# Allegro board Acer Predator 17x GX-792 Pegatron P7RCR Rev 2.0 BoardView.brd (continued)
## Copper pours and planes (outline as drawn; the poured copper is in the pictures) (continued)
PS_NVVDD_PHASE3 on TOP (solid shape): 150.98,183.75 150.98,182.35 151.36,181.97 153.4,181.97 153.9,182.48 156.7,182.48 156.95,182.23 156.95,180.19 160.2,176.94 160.2,168.66 159.49,167.95 149.75,167.95 149.21,168.5 149.21,171.05 147.55,172.7 147.55,179.46 153.65,179.46 153.65,179.4 153.66,179.34 153.67,179.28 153.7,179.22 153.73,179.16 153.77,179.11 153.81,179.06 153.86,179.02 153.91,178.99 153.97,178.96 154.03,178.94 154.1,178.93 154.16,178.92 154.22,178.93 154.29,178.94 154.35,178.96 154.4,178.99 154.46,179.02 154.51,179.06 154.55,179.11 154.59,179.16 154.62,179.22 154.64,179.28 154.66,179.34 154.67,179.4 154.67,179.46 154.66,179.53 154.64,179.59 154.62,179.65 154.59,179.71 154.55,179.76 154.51,179.8 154.46,179.84 154.4,179.88 154.35,179.91 154.29,179.93 154.22,179.94 154.16,179.94 154.1,179.94 154.03,179.93 153.97,179.91 153.91,179.88 153.86,179.84 153.81,179.8 153.77,179.76 153.73,179.71 153.7,179.65 153.67,179.59 153.66,179.53 153.65,179.46 147.55,179.46 147.55,183.62 147.81,183.88 150.86,183.88
PS_NVVDD_PHASE3 on BOTTOM (solid shape): 160.21,176.25 160.21,168.28 159.47,167.53 149.73,167.53 148.34,168.92 148.34,175.47 148.38,175.51 148.99,175.51 149.39,175.9 150.18,176.7 159.77,176.7
PS_NVVDD_PHASE4 on TOP (solid shape): 170.75,165.16 170.75,165.05 170.68,164.97 169.57,164.97 169.07,164.47 169.07,164.27 169.03,164.23 168.21,164.23 168.21,164.9 168.51,165.21 170.7,165.21
PS_NVVDD_PHASE4 on TOP (solid shape): outline of 112 points within 159.75,167.95 173.21,181.34
PS_NVVDD_PHASE4 on BOTTOM (solid shape): 173.24,176.57 173.24,168.59 172.12,167.47 163.56,167.47 161.34,169.68 161.34,175.22 161.65,175.53 162.14,175.53 162.51,175.9 162.51,175.99 163.4,176.88 172.93,176.88
SURGE_IN_C on IN1 (solid shape): 297.27,153.26 297.27,147.68 298.05,146.9 298.05,145.27 297.69,144.91 296.18,144.91 295.52,145.57 295.52,152.75 293.64,154.63 292,154.63 291.89,154.75 291.89,155.93 292.04,156.07 294.45,156.07
VGA_DDR_BST1 on TOP (solid shape): 248.07,81.13 247.78,80.84 247.53,80.48 247.53,79.38 247.35,79.2 247.02,79.2 246.81,79.41 246.81,80.61 247.27,81.07 247.47,81.07 247.77,81.23 247.86,81.33 247.86,81.63 248.07,81.63
VGA_DDR_BST1_R on TOP (solid shape): 244.86,81.03 245.67,81.03 245.78,80.92 246.13,80.92 246.42,80.63 246.42,80.12 246.33,80.03 245.64,80.03 245.56,80.07 245.54,80.16 245.44,80.52 245.08,80.62 245.04,80.61 245.01,80.62 244.38,80.62 244.13,80.88 244.13,81.13 244.28,81.29 244.61,81.29
VGA_DDR_BST2 on TOP (solid shape): 247.44,85.84 247.44,85.21 248.03,84.61 248.08,84.53 248.08,83.96 247.86,83.96 247.86,84.06 246.95,84.98 246.95,85.84 247,85.9 247.38,85.9
VGA_DDR_BST2_R on TOP (solid shape): 245.82,86.18 246.24,86.18 246.53,85.89 246.53,85.35 246.46,85.28 245.02,85.28 244.87,85.43 244.87,86.58 245.05,86.76 245.24,86.76
VGA_DDR_HG1 on TOP (solid shape): 248.48,80.72 248.47,80.71 248.47,80.01 248.4,79.94 247.88,79.94 247.8,80.02 247.8,80.3 247.89,80.52 247.97,80.6 248.27,81.11 248.27,81.64 248.48,81.64
VGA_DDR_HG1_R on TOP (solid shape): 225.89,90.48 225.89,88.15 225.63,87.89 224.36,87.89 224.2,88.05 224.2,90.06 224.7,90.56 225.81,90.56
VGA_DDR_HG1_R on TOP (solid shape): 248.77,79.18 248.77,78.93 248.91,78.79 248.91,78.43 248.81,78.33 248.49,78.33 247.8,79.02 247.8,79.47 247.88,79.54 248.41,79.54
VGA_DDR_HG2 on TOP (solid shape): 248.37,88.06 248.37,86.63 248.3,86.21 248.46,85.81 248.45,85.69 248.48,85.57 248.48,85.5 248.48,85.49 248.48,84 248.27,84 248.27,84.62 248.14,84.89 247.73,85.3 247.73,86.07 247.58,86.23 247.58,88.04 247.78,88.25 248.19,88.25
VGA_DDR_HG2_R on TOP (solid shape): 247.08,87.87 247.17,87.78 247.17,86.88 247.1,86.81 246.09,86.81 245.75,87.15 245.75,87.69 245.93,87.87 246.92,87.87
VGA_DDR_HG2_R on TOP (solid shape): 242.09,91.1 242.09,90.71 241.93,90.54 240.01,90.54 239.89,90.42 238.88,90.42 238.77,90.53 238.77,91.14 238.78,91.16 238.78,91.6 239.11,91.93 241.26,91.93
VGA_DDR_LG1 on TOP (solid shape): 247.59,82.33 247.04,82.33 246.91,82.25 246.51,81.85 246.26,81.85 245.97,82.14 245.97,82.35 246.17,82.55 247.59,82.55
VGA_DDR_LG1 on BOTTOM (solid shape): 220.12,100.25 220.12,99.79 219.97,99.65 218.36,99.65 217.91,99.2 216.87,99.2 216.72,99.35 216.72,99.75 216.8,99.83 217.27,99.83 217.86,100.42 219.95,100.42
VGA_DDR_LG2 on TOP (solid shape): 246.63,83.59 247.04,83.34 247.58,83.34 247.58,83.12 246.78,83.12 246.55,83.23 245.21,83.23 245.06,83.38 245.06,83.81 245.19,83.94 246.27,83.94
VGA_DDR_LG2 on BOTTOM (solid shape): 246.75,85.06 246.75,83.89 246.2,83.34 245.29,83.34 244.33,84.3 244.33,85.68 244.46,85.81 246.01,85.81
VGA_DDR_LX1 on TOP (solid shape): 225.86,96.78 225.86,95.51 226.12,95.26 226.12,94.83 225.86,94.57 225.86,91.27 225.79,91.19 224.43,91.19 223.8,90.56 219.25,90.56 218.79,91.02 218.79,94.95 219.21,95.37 219.21,96.86 219.59,97.24 220.96,97.24 221.04,97.31 225.33,97.31
VGA_DDR_LX1 on TOP (solid shape): 246.09,81.55 246.59,81.55 246.87,81.72 247.04,82.04 247.04,82.1 247.07,82.14 247.62,82.14 247.62,81.67 247.51,81.5 247.14,81.29 246.9,81.17 245.85,81.17 245.55,81.46 244.38,81.46 244.3,81.54 244.3,82 244.48,82.18 245.46,82.18
VGA_DDR_LX1 on BOTTOM (solid shape): 224.75,100.26 225.14,99.89 225.67,99.81 225.94,99.28 226.49,99.04 226.55,98.94 226.62,98.84 226.75,98.21 227.31,97.9 227.31,90.91 226.96,90.57 219.26,90.57 218.75,91.08 218.75,94.83 219.01,95.1 219.63,95.1 220.02,95.48 220.37,95.48 221.07,96.18 221.07,99.85 221.48,100.26
VGA_DDR_LX2 on TOP (solid shape): 244.61,86.98 244.61,85.45 245.08,84.98 246.25,84.98 247.49,83.73 247.59,83.73 247.59,83.52 247.07,83.52 246.92,83.64 246.31,84.24 243.9,84.24 243.49,83.83 240.62,83.83 239.43,82.64 239.43,82.57 239.21,82.35 238.09,82.35 238.08,82.35 237.8,82.35 237.8,82.35 237.23,82.35 236.78,82.8 236.6,82.8 236.56,82.84 235.59,82.84 235.46,82.97 235.46,86.1 235.64,86.27 238.39,86.27 238.77,86.65 238.77,89.59 238.94,89.77 240.14,89.77 240.27,89.91 241.68,89.91
VGA_DDR_LX2 on BOTTOM (solid shape): 233.79,94.47 238.74,94.47 239.12,94.09 239.76,94.09 239.96,93.89 239.96,90.66 240.42,90.2 242.96,90.2 243.59,89.57 243.59,85.22 241.29,82.93 241.29,82.04 240.39,81.13 236.45,81.13 236.2,81.39 236.2,82.9 236.07,83.03 236.07,85.1 236.02,85.15 236.02,85.66 235.82,85.86 234.1,85.86 229.08,90.88 228.23,90.88 228.07,91.04 228.07,94.47 228.2,94.6 233.66,94.6
VGA_DDR_RC1 on TOP (solid shape): 222.28,99.23 222.28,97.97 222.13,97.82 220.73,97.82 220.52,98.03 220.07,98.03 220.02,98.09 220.02,98.87 220.7,99.55 221.97,99.55
VGA_DDR_RC2 on BOTTOM (solid shape): 242.55,91.8 242.55,90.91 242.37,90.74 240.98,90.74 240.87,90.84 240.87,92.01 240.96,92.09 242.26,92.09
VGA_DDR_VCCP on TOP (solid shape): 245.03,83.05 246.47,83.05 246.71,82.94 247.59,82.94 247.59,82.73 246.47,82.73 246.39,82.74 246.3,82.73 245.88,82.73 245.57,82.42 244.25,82.42 244.07,82.6 244.07,83.14 244.23,83.3 244.78,83.3
VID_PLLVDD_GPU_AW27 on TOP (solid shape): 149.92,84.44 149.92,83.33 149.85,83.26 149.25,83.26 149.04,83.06 149.02,83.06 148.87,83.04 148.74,82.95 148.45,82.95 148.25,83.02 148.05,82.95 147.84,82.95 147.61,83.04 147.37,82.95 145.72,82.95 145.06,82.29 145.05,82.09 145.06,81.91 143.57,80.42 143.57,80.42 143.08,79.94 141.23,79.94 140.82,80.35 139.91,80.35 139.81,80.45 139.81,80.83 139.9,80.92 140.91,80.92 141.08,80.75 142.73,80.75 143.39,81.41 143.39,81.92 143.52,82.05 144.08,82.05 145.67,83.64 146.8,83.64 146.81,83.64 147,83.6 147.19,83.64 147.2,83.64 147.6,83.64 147.72,83.76 148.18,83.76 148.19,83.76 148.42,83.76 148.6,83.9 148.83,83.9 149.3,83.87 149.39,84.33 149.38,84.34 149.38,84.41 149.43,84.46 149.89,84.46
VID_PLLVDD_GPU_AW28 on TOP (solid shape): 150.51,84.3 150.57,84.19 150.66,84.12 150.66,81.84 150.52,81.7 150,81.7 149.32,81.02 145.45,81.02 145.36,80.93 145.35,80.92 145.25,80.85 145.17,80.75 145.17,80.74 144.82,80.39 144.81,80.39 144.68,80.3 144.6,80.17 144.59,80.16 144.53,80.1 144.53,79.08 144.35,78.9 143.69,78.9 143.64,78.95 143.64,80.23 145.14,81.73 146.05,81.73 146.24,81.68 146.43,81.73 146.69,81.73 146.7,81.73 146.85,81.69 147,81.73 147.01,81.73 148.06,81.73 148.27,81.64 148.5,81.71 148.53,81.73 149.29,81.73 149.52,81.96 149.64,81.96 149.95,82.28 149.98,82.28 149.98,82.42 150.06,82.51 150.06,84.17 150.23,84.34 150.48,84.34
VLDOIN on TOP (solid shape): 27.9,55.01 27.9,53.06 27.44,52.6 27.44,51.41 27.4,51.37 27.21,51.37 27.16,51.41 27.16,51.93 26.96,52.13 26.96,54.93 27.08,55.06 27.84,55.06
N60250715 on TOP (solid shape): 259.35,83.76 259.35,83.16 259.31,83.12 259.31,83.09 259.26,82.91 259.31,82.73 259.31,82.72 259.31,82.68 259.34,82.66 259.34,81.9 259.29,81.85 259.19,81.85 259.16,81.87 259.16,82.58 258.81,82.94 258.81,83.78 258.86,83.83 259.29,83.83
N60250719 on TOP (solid shape): 260.33,83.67 260.33,82.81 260.13,82.61 260.13,81.9 260.08,81.85 259.98,81.85 259.95,81.87 259.95,82.68 260.03,82.9 259.92,83.18 259.86,83.23 259.7,83.39 259.7,83.78 259.75,83.83 260.18,83.83
N65023456 on TOP (solid shape): 12.21,75.16 12.21,72.94 11.84,72.57 9.62,72.57 8.59,73.59 8.59,75.72 8.74,75.88 11.49,75.88
N125034509 on BOTTOM (solid shape): outline of 272 points within 76.09,113.65 79.79,118.27
N125034565 on TOP (solid shape): 80.28,122.22 80.28,121.7 80.32,121.66 80.32,121.41 80.15,121.24 79.21,121.24 79.03,121.06 77.87,121.06 77.74,121.19 77.74,121.6 77.82,121.67 78.94,121.67 79.04,121.78 79.04,121.84 79.66,122.46 80.04,122.46
N125034565 on BOTTOM (solid shape): 77.98,123.13 78,123.1 78,122.93 78.08,122.84 78.72,122.84 79.2,122.36 80,122.36 80.41,121.95 80.41,121.44 80.28,121.32 78.25,121.32 78,121.06 78,120.99 77.99,120.98 77.97,120.86 77.99,120.74 78,120.73 78,120.2 77.99,120.19 77.97,120.07 77.99,119.95 78,119.92 78.06,119.85 78.12,119.79 78.15,119.79 78.29,119.75 78.43,119.79 78.44,119.79 78.79,119.79 78.8,119.79 78.94,119.75 79.08,119.79 79.09,119.79 79.25,119.79 79.29,119.77 79.39,119.67 79.39,119.03 79.27,118.9 77.74,118.9 77.66,118.99 77.65,119 77.56,119.14 77.42,119.23 77.41,119.24 77.28,119.36 77.27,119.41 77.27,119.47 77.02,119.72 77.01,119.74 76.93,119.92 76.76,120.02 76.73,120.03 76.73,120.3 76.98,120.55 77,120.56 77.19,120.63 77.29,120.82 77.29,120.83 77.35,120.9 77.37,120.9 77.66,121.19 77.49,121.56 77.49,122.52 77.67,122.83 77.49,123.14 77.49,123.3 77.5,123.31 77.54,123.34 77.58,123.37 77.74,123.37
N126075660 on BOTTOM (solid shape): 239.27,49.9 239.27,49.79 240.06,49 241.08,49 241.48,48.6 242.42,48.6 242.73,48.9 245.31,48.9 245.32,48.9 245.32,48.39 245.31,48.38 243.41,48.38 243.41,48.38 242.81,48.38 242.32,47.89 241.36,47.89 241.36,47.9 240.87,48.38 239.6,48.38 239.09,48.89 238.93,48.91 238.93,49.06 238.93,49.23 238.82,49.33 238.82,49.37 238.78,49.41 238.78,50.06 238.88,50.16 239.02,50.16
N126076879 on IN2 (solid shape): outline of 658 points within 227.77,46.03 239.76,50.76
N126273757 on TOP (solid shape): 77.54,111.98 77.54,111.66 77.34,111.46 76.79,111.46 76.59,111.47 76.4,111.4 76.38,111.39 75.39,110.4 74.96,110.4 74.86,110.5 74.86,110.88 75.16,111.18 75.52,111.18 75.52,111.19 75.67,111.19 75.74,111.26 75.74,112.1 75.79,112.15 77.37,112.15
N126721746 on BOTTOM (solid shape): 74.81,113.57 75.04,113.47 75.26,113.57 75.46,113.57 75.6,113.48 75.76,113.48 75.79,113.49 75.96,113.32 75.96,113.06 75.71,112.81 74.17,112.81 74.1,112.88 74.1,113.1 74.46,113.46 74.47,113.47 74.56,113.51 74.63,113.57
N126721910 on BOTTOM (solid shape): 75.71,113.98 75.77,113.91 75.84,113.86 75.84,113.7 75.75,113.61 75.69,113.6 75.64,113.6 75.36,113.74 75.08,113.6 75.03,113.6 74.99,113.6 74.7,113.74 74.43,113.59 74.34,113.59 74.09,113.35 73.63,113.35 73.55,113.44 73.55,113.73 73.79,113.98
N129963392 on TOP (solid shape): 2.77,30.69 2.77,30.44 2.52,30.18 2.52,29.12 2.27,28.86 2.27,28.85 2.15,28.37 2.57,28.13 2.9,27.79 3.53,27.79 3.89,27.64 4.26,27.79 4.43,27.79 4.55,27.67 4.55,25.99 2.39,23.83 2.39,20.43 2.27,20.3 2.27,19.16 2.14,19.03 1.25,19.03 1.14,19.14 1.14,20.74 1.15,20.81 1.14,20.88 1.14,23.28 1.15,23.35 1.14,23.42 1.14,24.26 1.38,24.49 1.81,24.49 1.96,24.65 1.96,27.72 1.61,28.07 1.61,29.27 1.86,29.52 1.86,30.59 2.06,30.79 2.67,30.79
N136259332 on TOP (solid shape): 301.83,48.6 301.83,47.2 301.48,46.84 299.6,46.84 298.71,45.96 298.71,45.3 298.63,45.22 298.46,45.22 298.38,45.3 298.38,45.32 298.32,45.51 298.14,45.6 298.12,45.6 298.08,45.65 298.08,45.89 298.09,45.9 298.09,46.22 298.43,46.83 298.43,48.52 298.58,48.67 301.76,48.67
N138947971 on BOTTOM (solid shape): 66.26,149.67 66.26,148.73 66.58,148.41 66.65,148.41 66.67,148.39 66.67,148 66.62,147.95 66.3,147.95 66.27,147.98 66.27,148.35 65.75,148.87 65.75,149.76 66.17,149.76
N138948726 on BOTTOM (solid shape): 68.1,149.33 68.19,149.33 68.86,149.33 68.91,149.28 68.91,149.12 68.82,149.04 67.73,149.04 67.59,148.9 67.13,148.9 67.07,148.96 67.07,149.72 67.1,149.75 67.68,149.75
N138949618 on BOTTOM (solid shape): 75.8,155.3 75.8,153.4 75.67,153.27 74.66,153.27 74.4,153.52 74.4,155.3 74.53,155.43 75.67,155.43
N138973117 on BOTTOM (solid shape): 79.85,182.52 80.53,182.52 80.61,182.44 80.61,181.8 80.51,181.7 80.09,181.7 79.81,181.97 79.81,182.13 79.74,182.2 79.28,182.2 79.24,182.24 79.24,182.59 79.27,182.61 79.75,182.61
N138973150 on BOTTOM (solid shape): 81.91,182.45 81.91,181.72 81.17,180.98 80.82,180.98 80.62,180.78 80.62,180 80.58,179.96 80.37,179.96 80.33,180 80.33,181.11 80.76,181.54 81.26,181.54 81.41,181.69 81.41,182.5 81.43,182.52 81.84,182.52
N138973270 on BOTTOM (solid shape): 86.34,174.99 86.34,173.72 86.21,173.59 85.58,173.59 85.45,173.72 85.45,174.61 85.32,174.73 84.56,174.73 84.44,174.86 84.44,176.13 85.2,176.13
N138993779 on BOTTOM (solid shape): 66.5,168.19 66.5,167.39 66.63,167.27 66.75,167.27 66.92,167.1 66.92,166.54 66.83,166.45 66.52,166.45 65.97,167 65.97,168.21 66.03,168.27 66.43,168.27
N138993811 on BOTTOM (solid shape): 68.22,167.87 69.13,167.87 69.16,167.84 69.16,167.64 69.11,167.59 68,167.59 67.87,167.46 67.35,167.46 67.31,167.5 67.31,168.24 67.36,168.29 67.81,168.29
N138993942 on BOTTOM (solid shape): 75.93,170.54 75.93,168.76 75.8,168.64 74.78,168.64 74.66,168.76 74.66,170.54 74.78,170.67 75.8,170.67
N139090834 on TOP (solid shape): 92.17,159.52 92.17,158.34 92.04,158.21 90.83,158.21 90.31,158.73 90.31,159.52 90.38,159.6 92.09,159.6
N143634716 on BOTTOM (solid shape): 185.95,170.17 185.95,168.88 185.87,168.79 185.2,168.79 185.1,168.89 185.1,170.19 185.14,170.24 185.89,170.24
N143636053 on BOTTOM (solid shape): 210.74,172.87 210.74,171.75 210.58,171.59 210.08,171.59 209.92,171.75 209.92,172.93 209.99,173 210.6,173
N143646420 on TOP (solid shape): 184.6,163.88 184.6,162.14 184.45,161.99 183.96,161.99 183.94,162.01 183.94,162.96 184.14,163.16 184.14,163.81 184.26,163.93 184.56,163.93
N143646442 on TOP (solid shape): 183.09,162.78 183.09,162.11 182.98,162 180.72,162 180.71,162 180.43,162 180.34,162.09 180.34,162.55 180.44,162.65 182.38,162.65 182.59,162.85 183.02,162.85
N143646485 on TOP (solid shape): 182.82,163.87 182.82,163.48 182.26,162.92 181.69,162.92 181.46,163.15 181.46,163.51 181.84,163.89 182.3,163.89 182.35,163.94 182.75,163.94
N143646485 on TOP (solid shape): 177.15,181.21 177.15,180.19 177.02,180.07 175.75,180.07 175.62,180.19 175.62,181.27 175.69,181.34 177.02,181.34
N143646485 on TOP (solid shape): 184.03,181.13 184.03,180.47 183.62,180.07 181.67,180.07 181.59,180.15 181.59,181.27 181.66,181.34 183.83,181.34
N143646495 on BOTTOM (solid shape): 179.63,179.65 179.63,177.7 179.58,177.65 178.76,177.65 178.75,177.66 178.75,179.65 178.93,179.83 179.45,179.83
N143646495 on BOTTOM (solid shape): 185.6,179.65 185.6,179.11 185.3,178.82 185.3,177.78 185.17,177.65 184.73,177.65 184.72,177.66 184.72,179.65 184.9,179.83 185.42,179.83
N143742448 on BOTTOM (solid shape): 186.22,180.62 187.89,180.62 188.26,180.25 188.26,179.99 188.1,179.83 187.32,179.83 187.05,180.09 185.77,180.09 185.72,180.04 185.36,180.04 185.2,180.21 185.2,180.8 185.26,180.86 185.98,180.86
N143746856 on BOTTOM (solid shape): 140.6,179.59 140.6,177.73 140.52,177.66 139.4,177.66 139.4,179.27 139.95,179.82 140.37,179.82
N143746856 on BOTTOM (solid shape): 146.53,179.58 146.53,177.71 146.48,177.65 145.41,177.65 145.35,177.72 145.35,179.2 145.94,179.79 146.32,179.79
N143746974 on TOP (solid shape): 145.15,164.65 145.15,162.91 145,162.75 144.51,162.75 144.49,162.77 144.49,163.72 144.7,163.92 144.7,164.57 144.82,164.69 145.11,164.69
N143746980 on TOP (solid shape): 143.65,163.54 143.65,162.87 143.53,162.76 140.96,162.76 140.88,162.84 140.88,163.31 140.98,163.41 142.94,163.41 143.14,163.61 143.58,163.61
N143747012 on TOP (solid shape): 132.65,174.58 132.65,172.99 132.37,172.71 131.75,172.71 131.55,172.91 131.55,174.61 131.69,174.75 132.48,174.75
N143747012 on TOP (solid shape): 140.17,174.32 140.17,173.67 139.97,173.47 137.88,173.47 137.65,173.7 137.65,174.63 137.75,174.73 139.75,174.73
N143747012 on TOP (solid shape): 143.38,164.63 143.38,164.24 142.82,163.68 142.25,163.68 142.02,163.91 142.02,164.28 142.39,164.65 142.85,164.65 142.9,164.7 143.3,164.7
N143747152 on BOTTOM (solid shape): 147.79,177.62 147.79,176.46 147.69,176.36 147.24,176.36 147.05,176.55 147.05,177.62 147.14,177.71 147.7,177.71
N143748104 on BOTTOM (solid shape): 154.61,179.65 154.61,177.7 154.57,177.65 153.74,177.65 153.73,177.66 153.73,179.65 153.91,179.83 154.43,179.83
N143748104 on BOTTOM (solid shape): 160.58,179.65 160.58,177.7 160.54,177.65 159.71,177.65 159.7,177.66 159.7,179.65 159.88,179.83 160.4,179.83
N143748222 on TOP (solid shape): 159.58,164.65 159.58,164.05 160.39,163.24 160.39,162.89 160.25,162.75 158.94,162.75 158.92,162.77 158.92,163.72 159.12,163.92 159.12,164.57 159.24,164.69 159.54,164.69
N143748228 on TOP (solid shape): 158.07,163.54 158.07,162.87 157.96,162.76 155.39,162.76 155.31,162.84 155.31,163.31 155.4,163.41 157.36,163.41 157.57,163.61 158,163.61
N143748260 on TOP (solid shape): 153.27,183.75 153.27,182.73 153.14,182.61 151.75,182.61 151.75,183.88 153.14,183.88
N143748260 on TOP (solid shape): 157.8,164.63 157.8,164.24 157.25,163.68 156.67,163.68 156.44,163.91 156.44,164.28 156.82,164.65 157.28,164.65 157.33,164.7 157.73,164.7
N143748260 on TOP (solid shape): 159.24,182.1 159.24,180.3 158.78,179.84 158.2,179.84 157.71,180.32 157.71,182.16 157.78,182.23 159.11,182.23
N143748400 on BOTTOM (solid shape): 149.1,177.64 149.1,176.38 149.03,176.31 148.39,176.31 148.31,176.39 148.31,177.64 148.39,177.72 149.01,177.72
N143749353 on BOTTOM (solid shape): 167.75,179.65 167.75,177.7 167.7,177.65 166.88,177.65 166.86,177.66 166.86,179.65 167.05,179.83 167.56,179.83
N143749353 on BOTTOM (solid shape): 173.66,179.65 173.66,177.7 173.61,177.65 172.79,177.65 172.78,177.66 172.78,179.65 172.96,179.83 173.48,179.83
N143749471 on TOP (solid shape): 172.54,164.65 172.54,163.84 173.3,163.08 173.3,162.73 173.21,162.65 172.64,162.65 172.54,162.75 171.89,162.75 171.87,162.77 171.87,163.72 172.08,163.92 172.08,164.57 172.2,164.69 172.49,164.69
N143749477 on TOP (solid shape): 171.03,163.54 171.03,162.87 170.91,162.76 168.34,162.76 168.26,162.84 168.26,163.31 168.36,163.41 170.32,163.41 170.52,163.61 170.96,163.61
N143749509 on TOP (solid shape): 165.21,181.21 165.21,180.19 165.08,180.07 163.68,180.07 163.68,181.34 165.08,181.34
N143749509 on TOP (solid shape): 170.76,164.63 170.76,164.24 170.2,163.68 169.63,163.68 169.4,163.91 169.4,164.28 169.77,164.65 170.23,164.65 170.28,164.7 170.68,164.7
N143749509 on TOP (solid shape): 171.18,181.21 171.18,179.15 171.05,179.03 170.82,179.03 169.65,180.19 169.65,181.26 169.73,181.34 171.05,181.34
N143749649 on BOTTOM (solid shape): 162.15,177.66 162.15,176.43 162.07,176.34 161.53,176.34 161.38,176.48 161.38,177.66 161.46,177.73 162.08,177.73
N144850446 on TOP (solid shape): 225.58,17.81 225.58,16.83 225.14,16.39 225.14,15.7 225.12,15.68 224.89,15.68 224.88,15.7 224.88,17.7 225.01,17.83 225.57,17.83
N144852564 on BOTTOM (solid shape): 123.55,60.61 123.55,59.82 123.44,59.71 122.34,59.71 121.85,60.21 121.85,60.64 121.98,60.77 123.38,60.77
N144852791 on TOP (solid shape): 117.11,64.42 117.11,63.4 117.35,63.16 117.35,61.95 116.95,61.55 116.72,61.55 116.04,62.23 116.04,64.39 116.1,64.46 117.07,64.46
N144854261 on BOTTOM (solid shape): 103.55,171.27 103.55,170.93 103.42,170.8 103.3,170.82 103.17,170.8 103,170.8 102.49,170.28 102.49,169.38 102.46,169.35 102.26,169.35 102.23,169.38 102.23,170.34 102.07,170.51 102.07,171.29 102.12,171.34 103.48,171.34
N144858298 on TOP (solid shape): 99.93,9.51 99.93,4.38 98.81,3.26 96.38,3.26 94.77,4.87 93.15,4.87 92.86,5.17 91.24,5.17 91.13,5.27 90.3,5.27 90.19,5.39 90.19,6.07 90.23,6.11 92.65,6.11 92.86,6.32 92.86,6.76 92.92,6.82 94.19,6.82 94.49,7.12 94.49,10.2 94.81,10.52 98.91,10.52
N144858349 on TOP (solid shape): 94.98,3.57 94.98,2.27 94.84,2.13 93.72,2.13 93.57,2.29 93.57,2.86 93.14,3.28 93.14,3.9 93.27,4.02 94.52,4.02
N144858623 on TOP (solid shape): 94.09,10.22 94.09,9.63 93.86,9.41 93.87,9.4 93.87,7.68 93.74,7.56 92.94,7.56 92.88,7.62 92.88,8.23 93.14,8.5 93.14,10.11 93.38,10.34 93.96,10.34
N144865773 on TOP (solid shape): 56.92,167.9 57.44,167.9 57.51,167.83 57.51,167.46 57.46,167.41 57.04,167.41 56.19,168.25 55.32,168.25 55.3,168.27 55.3,168.47 55.34,168.51 56.31,168.51
N144865775 on TOP (solid shape): 57.56,170.97 57.56,170.55 57.49,170.48 56.92,170.48 56.52,170.08 56.52,169.5 56.26,169.24 55.32,169.24 55.29,169.26 55.29,169.5 55.31,169.52 56.06,169.52 56.14,169.59 56.14,169.6 56.17,169.64 56.17,170.16 56.14,170.16 56.14,170.74 56.41,171.01 57.51,171.01
N144865830 on TOP (solid shape): 49.76,171.56 49.76,170.67 49.64,170.54 48.49,170.54 48.37,170.67 48.37,170.85 47.53,171.69 47.53,172.14 47.71,172.32 49,172.32
N144866143 on TOP (solid shape): 61.7,165.46 61.7,164.32 61.66,164.28 59.72,164.28 59.67,164.32 59.67,165.46 59.8,165.59 61.58,165.59
N146002641 on TOP (solid shape): 103.38,190.14 103.38,188.89 103.38,188.47 103.38,188.47 103.38,187.8 103.14,187.8 103.13,187.81 103.13,188.9 103.12,188.9 102.88,188.9 102.88,188.9 102.88,187.8 102.64,187.8 102.64,189.43 102.47,189.59 101.93,189.59 101.75,189.78 101.75,190.23 101.97,190.46 103.06,190.46
N146002641 on BOTTOM (solid shape): 104.17,191.44 104.17,190.28 103.09,189.19 102.42,189.19 101.61,190 101.61,191.54 101.73,191.66 103.95,191.66
N152557460 on TOP (solid shape): 18.37,87.05 18.37,86.37 18.32,86.32 18.07,86.32 17.43,85.68 17.43,85.38 17.25,85.2 14.66,85.2 13.93,84.46 13.72,84.46 13.72,84.47 12.8,84.47 12.73,84.54 12.73,85.15 12.95,85.36 13.48,85.36 14.08,85.96 14.23,86.04 14.23,86.04 14.4,86.13 15.01,86.13 15.26,86.38 16.82,86.38 17.05,86.61 17.39,86.61 17.99,87.21 18.22,87.21
N157332809 on BOTTOM (solid shape): 18.78,65.14 18.78,64.39 18.72,64.33 18.46,64.33 18.46,64.32 16.64,64.32 16.07,63.75 11.35,63.75 11.28,63.81 11.28,64.47 11.36,64.54 15.59,64.54 16.27,65.23 18.7,65.23
N158267574 on TOP (solid shape): 122.39,134.76 122.39,133.05 122.93,132.52 122.93,124.17 122.82,124.06 121.7,124.06 120.98,124.78 120.98,130.07 120.8,130.25 120.8,134.43 120.84,134.49 120.87,134.55 121.17,134.85 122.3,134.85
N158267622 on TOP (solid shape): 205.24,139.21 205.24,137.82 203.33,135.92 203.33,135.76 203.18,135.61 203.18,133.8 203.16,133.78 203.16,132.04 203.04,131.93 202.39,131.93 202.25,132.07 202.25,140.47 202.43,140.64 203.81,140.64
N159618827 on TOP (solid shape): 295.51,100.06 295.51,99.31 295.41,99.21 292.91,99.21 292.78,99.34 292.78,99.74 293.22,100.19 293.22,101.07 293.3,101.15 294.42,101.15
N161419358 on BOTTOM (solid shape): outline of 227 points within 93.92,111 96.85,128.94
N162210915 on TOP (solid shape): 226.23,56.2 227.67,56.2 227.76,56.1 227.76,55.76 227.66,55.65 225.64,55.65 225.52,55.53 225.52,53.98 225.47,53.92 225.44,53.84 225.33,53.74 224.93,53.74 224.83,53.83 224.83,55.98 225.3,56.45 225.98,56.45
N169179480 on TOP (solid shape): 307.42,116.03 307.42,115.32 307.63,115.12 307.83,115.12 307.88,115.07 307.88,113.06 306.66,111.84 306.66,111.51 306.46,111.31 306.18,111.31 306.03,111.46 306.03,112.05 306.81,112.83 306.81,115.88 307.09,116.16 307.3,116.16
N170005185 on BOTTOM (solid shape): 199.58,58.37 199.58,51.08 199.45,50.95 198.36,50.95 198.21,51.1 198.21,58.29 198.41,58.49 199.45,58.49
N170416463 on TOP (solid shape): 14.08,63.52 14.08,62.97 13.94,62.83 13.44,62.83 13.38,62.77 13.38,61.26 13.29,61.18 10.99,61.18 10.41,61.76 10.41,62.67 10.53,62.79 12.21,62.79 13.02,63.6 14,63.6
N170416463 on BOTTOM (solid shape): 14.32,63.43 14.32,62.76 13.8,62.24 11.26,62.24 11.18,62.32 11.18,63.05 11.24,63.11 13.39,63.11 13.64,63.36 13.64,63.47 13.76,63.59 14.16,63.59
N170982679 on BOTTOM (solid shape): 134.75,171.05 134.75,168.23 134.6,168.08 130.82,168.08 130.47,168.43 130.47,168.93 130.82,169.27 132.47,169.27 132.85,169.65 132.85,171.13 132.92,171.2 134.6,171.2

Small or netless copper shapes (teardrops, artwork), in the pictures only: 3895 on TOP, 8515 on BOTTOM, 1109 on IN1, 573 on IN2, 431 on IN3, 1114 on IN4

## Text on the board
Ref Des/Silkscreen Bottom: PCB MADE IN | JP8050 | JP8051 | JP8054 | JP8055 | JP9401 | CON6004 | CON5100 | CON5103 | CON6701 | CON6003 | CON5104 | CON5102 | CON1701 | CON5000 | H64 | CON5602 | H61 | H66 | JP9400 | H65 | JP9402 | JP9601 | CON3100 | JP9600 | H63 | H60 | CON4400 | CON4402 | CON3110 | H69 | H68 | CON3104 | H805 | H803 | CON3700 | JP8109 | JP8108 | H804 | H800 | JP8105 | JP8107 | CON5001 | CON6000 | H62 | H6903 | H34 | H33 | CON2800 | CON3600 | CON6700 | CON6001 | CON1601 | CON5002 | JP8052 | JP8053 | JP8703 | JP8704 | JP8705 | JP8706 | JP8707 | JP8708 | JP8701 | JP8702 | JP8103 | JP8104 | CON5300 | CON6002 | CON3400 | BOT | 2nd
Ref Des/Silkscreen Top: P7RCR_LED_BD | TOP | CON1 | REV:2.0 | JP9301 | H51 | JP8301 | JP8300 | JP8801 | JP8802 | H71 | CON1600 | CON1700 | JP8305 | H31 | JP8307 | H70 | JP9300 | H32 | H6902 | JP5601 | JP9502 | JP9501 | JP9500 | JP8602 | H53 | CON4500 | JP8603 | JP8601 | H6901 | H54 | H36 | H35 | JP8200 | H56 | JP8202 | JP2601 | JP8400 | JP2602 | JP8102 | JP9302 | H52 | JP8112 | JP9303 | JP8111 | H55 | JP8110 | U3300 | JP8101 | C1131 | JP8804 | JP8805 | C1130 | H21 | JP8304 | JP8303 | JP8302 | JP8306 | JP8058 | JP8057 | JP1701 | JP1601 | JP8060 | JP8059 | JP1001 | JP8056 | JP8061 | JP9000 | JP8106 | JP8100 | JP8803 | CON4601 | CON5501 | CON5500 | CON4800 | JP8800 | CON1201 | H11 | 2.0/1050mils | 2016.1018 | R7505 | P7RCR MAIN BOARD | PCB MADE IN | 1st | P7RCR MAIN BOARD REV:2.0
User.28: 36 | 1 | 12 | 24 | 5 | 10 | 15 | 16 | 8 | 4 | 20 | 32 | 64 | 96 | P7RCR_LED_BD | TOP | CON1 | REV:1.1 | 6 | 11 | 14 | 7 | 21 | 30 | 9 | 13 | 38 | JP9301 | 17 | 2 | H51 | JP8301 | JP8300 | JP8801 | JP8802 | H71 | CON1600 | CON1700 | JP8305 | H31 | JP8307 | H70 | JP9300 | H32 | H6902 | JP5601 | JP9502 | JP9501 | JP9500 | 260 | JP8602 | H53 | CON4500 | JP8603 | JP8601 | H6901 | H54 | H36 | H35 | JP8200 | H56 | JP8202 | JP2601 | JP8400 | JP2602 | JP8102 | JP9302 | H52 | JP8112 | JP9303 | JP8111 | H55 | JP8110 | JP8101 | JP8804 | JP8805 | H21 | JP8304 | JP8303 | JP8302 | JP8306 | JP8058 | JP8057 | JP1701 | JP1601 | JP8060 | JP8059 | JP1001 | JP8056 | JP8061 | 259 | JP9000 | JP8106 | JP8100 | JP8803 | CON4601 | CON5501 | CON5500 | CON4800 | JP8800 | CON1201 | A1 | PEGATRON PROPRIETARY AND CONFIDENTIAL | TEL:(02)81439001 FAX:(02)28973868 | TAIPEI | www.pegatroncorp.com | DESIGNED BY PEGATRON CORPORATION | H11 | 1.1/650MILS | 2016.0721 | DESIGNER: | DATE: | LAY#: | 2016.07.21/12:30:37 | G1-P7RCR.11 | JASON1_LIAO | P7RCR MAIN BOARD | PCB MADE IN | R&D DEPARTMENT/ENGINEER: | PROJECT DESCRIPTION: | MODEL NAME: | P7RCR | BG1-NB4_OEM1/ Kai Shen | MAIN BOARD | REV. | 1.1 | SILKSCREEN | PRIMARY-SIDE | 1st | P7RCR MAIN BOARD REV:1.1
User.29: 1 | 8 | 16 | 24 | PCB MADE IN | JP8050 | JP8051 | JP8054 | JP8055 | JP9401 | 9 | 7 | 2 | CON6004 | CON5100 | CON5103 | CON6701 | CON6003 | CON5104 | CON5102 | CON1701 | 50 | 30 | 20 | 40 | 10 | 60 | CON5000 | 12 | 5 | 15 | 25 | 35 | 45 | H64 | CON5602 | H61 | H66 | JP9400 | 259 | 260 | H65 | JP9402 | JP9601 | CON3100 | JP9600 | H63 | H60 | CON4400 | CON4402 | CON3110 | H69 | H68 | CON3104 | H805 | H803 | CON3700 | JP8109 | JP8108 | H804 | H800 | JP8105 | JP8107 | CON5001 | CON6000 | H62 | H6903 | H34 | H33 | CON2800 | 36 | CON3600 | CON6700 | CON6001 | CON1601 | 55 | CON5002 | JP8052 | JP8053 | JP8703 | JP8704 | JP8705 | JP8706 | JP8707 | JP8708 | JP8701 | JP8702 | JP8103 | JP8104 | CON5300 | CON6002 | CON3400 | PEGATRON PROPRIETARY AND CONFIDENTIAL | TEL:(02)81439001 FAX:(02)28973868 | TAIPEI | www.pegatroncorp.com | DESIGNED BY PEGATRON CORPORATION | DESIGNER: | DATE: | LAY#: | 2016.07.21/12:30:37 | G1-P7RCR.11 | JASON1_LIAO | BOT | R&D DEPARTMENT/ENGINEER: | PROJECT DESCRIPTION: | MODEL NAME: | P7RCR | BG1-NB4_OEM1/ Kai Shen | MAIN BOARD | REV. | 1.1 | SILKSCREEN | SECONDARY-SIDE | 2nd
User.45: FIGURE | SIZE | 8.0 | 10.0 | 12.0 | 16.0 | 18.0 | 21.0 | 22.0 | 27.0 | 29.0 | 118.0 | 130.0 | 146.0 | 30.0 | 34.0 | 36.0 | 40.0 | 41.0 | 43.0 | 49.0 | 63.0 | 102.0 | 160.0 | 32.0x18.0 | 47.0x24.0 | 57.0x18.0 | 63.0x24.0 | 77.0x22.0 | 77.0x30.0 | 94.0x28.0 | 101.0x22.0 | 122.0x102.0 | 134.0x102.0 | DRILL CHART: TOP to BOTTOM (1 to 14) | ALL UNITS ARE IN MILS | TOLERANCE | +3.0/-3.0 | +2.0/-2.0 | PLATED | NON-PLATED | ROTATION | - | 90.000 | 0.000 | QTY | 2865 | 7452 | 119 | 12 | 2051 | 20 | 19 | 8 | 18 | 4 | 5 | 2 | 3 | 6 | 1 | 12650 | TOTAL HOLES:
